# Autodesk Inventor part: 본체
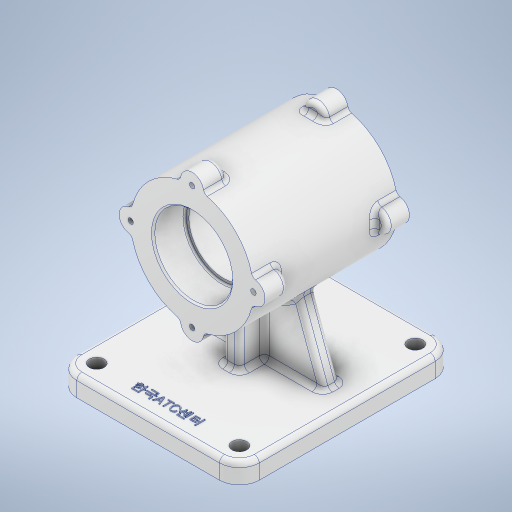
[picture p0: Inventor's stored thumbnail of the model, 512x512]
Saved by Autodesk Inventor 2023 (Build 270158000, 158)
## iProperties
Created: 2023-08
Part Number: 본체
Material: 알루미늄 6061
Document SubType Name: Modeling
Designer: asung
Density: 2.7 g/cm^3
Appearance: 알루미늄 - 평지
Author: asung
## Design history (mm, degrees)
sketch "스케치1"
  geometry: L1 (-43, 65)-(43, 65); L2 (55, 53)-(55, -53); L3 (43, -65)-(-43, -65); L4 (-55, -53)-(-55, 53); L5 (-55, 65)-(55, -65); L6 (55, 65)-(-55, -65); C1 r 4.5 at (43, 53); C2 r 4.5 at (-43, 53); C3 r 4.5 at (-43, -53); C4 r 4.5 at (43, -53); A1 r 12 centre (43, 53) between (55, 53) and (43, 65); A2 r 12 centre (43, -53) between (43, -65) and (55, -53); A3 r 12 centre (-43, -53) between (-55, -53) and (-43, -65); A4 r 12 centre (-43, 53) between (-43, 65) and (-55, 53); 1 further point
  constraints: 12 end point, 8 centre point, 8 point on circle, 8 point on line, 8 tangent, 4 coincident, 3 equal radius, 2 midpoint, 2 parallel, 1 horizontal, 1 perpendicular
  dimensions: "d0" = 110 distance of L5.end L6.end; "d1" = 130 distance of L6.start L5.end; "d2" = 12 radius of A1; "d3" = 9 diameter of C1; "d4" = 9 diameter of C2; "d5" = 9 diameter of C3; "d6" = 9 diameter of C4
extrude "돌출1" new body sketch "스케치1" distance "d7" = 12; taper "d8" = 0 deg
fillet "모깎기1" dims "d9" = 3
node "작업 평면1"
sketch "스케치2"
  geometry: L1 (-9, 12)-(95, 12) reference; L2 (98, 9)-(98, 0) reference; L3 (98, 0)-(-12, 0) reference; L4 (-12, 0)-(-12, 9) reference; L5 (86, 0)-(0, 0) reference; L6 (43, 0)-(43, 82); C1 r 37 at (43, 82); A1 r 3 centre (-9, 9) between (-9, 12) and (-12, 9) reference; A2 r 3 centre (95, 9) between (98, 9) and (95, 12) reference
  constraints: 2 end point, 1 centre point, 1 coincident, 1 vertical
  dimensions: "d14" = 82 distance of L6.start L6.end; "d15" = 37 radius of C1
extrude "돌출2" join sketch "스케치2" stored distance "d16" = 87; taper "d17" = 0 deg
sketch "스케치3"
  geometry: C1 r 37 at (0, 0) reference; C2 r 7 at (0, 37); 2 further points
  constraints: 1 centre point, 1 vertical alignment, 1 other
  dimensions: "d18" = 7 radius of C2
extrude "돌출3" join sketch "스케치3" distance "d19" = 14; taper "d20" = 0 deg
sketch "스케치4"
  geometry: C1 r 37 at (0, 0) reference; C2 r 7 at (0, 37); 2 further points
  constraints: 1 centre point, 1 vertical alignment, 1 other
  dimensions: "d24" = 7 radius of C2
extrude "돌출4" join sketch "스케치4" distance "d25" = 14; taper "d26" = 0 deg
fillet "모깎기2" dims "d30" = 3
fillet "모깎기3" dims "d34" = 3
sketch "스케치5"
  geometry: A1 r 37 centre (43, 82) between (78.863, 91.104) and (52.104, 117.863) reference; 2 further points
  constraints: 1 coincident
hole "구멍1" sketch "스케치5" at (43, 82) diameter "d38" = 42; stored, may be unused: countersink angle "d42" = 90 deg, drill point angle "d44" = 0 deg; dims "d39" = 8, "d40" = 47, "d41" = 19, "d43" = 50
sketch "스케치6"
  geometry: A1 r 37 centre (-43, 82) between (-52.104, 117.863) and (-78.863, 91.104) reference; 2 further points
  constraints: 1 coincident
hole "구멍2" sketch "스케치6" at (-43, 82) diameter "d45" = 42; stored, may be unused: countersink angle "d49" = 90 deg, drill point angle "d51" = 0 deg; dims "d46" = 6, "d47" = 47, "d48" = 19, "d50" = 50
fillet "모깎기4" dims "d52" = 1
chamfer "모따기1" distance "d53" = 1; stored, may be unused: second distance "d54" = 2, angle "d55" = 45 deg
sketch "스케치7"
  geometry: A1 r 7 centre (43, 119) between (49.889, 120.239) and (36.111, 120.239) reference; A2 r 7 centre (6, 82) between (4.761, 88.889) and (4.761, 75.111) reference; A3 r 7 centre (80, 82) between (81.239, 75.111) and (81.239, 88.889) reference; A4 r 7 centre (43, 45) between (36.111, 43.761) and (49.889, 43.761) reference; 5 further points
  constraints: 4 coincident
hole "구멍3" sketch "스케치7" at (43, 119), (6, 82), (80, 82), (43, 45) diameter "d56" = 3.242; stored, may be unused: countersink angle "d60" = 90 deg, drill point angle "d62" = 118 deg; dims "d57" = 8, "d58" = 47, "d59" = 19, "d61" = 10
sketch "스케치8"
  geometry: A1 r 7 centre (-43, 119) between (-36.111, 120.239) and (-49.889, 120.239) reference; A2 r 7 centre (-6, 82) between (-4.761, 75.111) and (-4.761, 88.889) reference; A3 r 7 centre (-43, 45) between (-49.889, 43.761) and (-36.111, 43.761) reference; A4 r 7 centre (-80, 82) between (-81.239, 88.889) and (-81.239, 75.111) reference; 5 further points
  constraints: 4 coincident
hole "구멍4" sketch "스케치8" at (-43, 119), (-6, 82), (-43, 45), (-80, 82) diameter "d63" = 3.242; stored, may be unused: countersink angle "d67" = 90 deg, drill point angle "d69" = 118 deg; dims "d64" = 8, "d65" = 4, "d66" = 2, "d68" = 10
sketch "스케치9"
  geometry: L1 (52, -53)-(52, 53) reference; L2 (43, 62)-(-43, 62) reference; L3 (-52, 53)-(-52, -53) reference; L4 (-43, -62)-(43, -62) reference; L5 (-5, -15)-(5, -15); L6 (5, -15)-(5, 25); L7 (5, 25)-(-5, 25); L8 (-5, 25)-(-5, -15); L9 (-43, -65)-(43, -65) reference; L10 (-55, 53)-(-55, -53) reference; C1 r 4.5 at (-43, -53) reference; C2 r 4.5 at (43, -53) reference; C3 r 4.5 at (43, 53) reference; C4 r 4.5 at (-43, 53) reference; A1 r 9 centre (43, -53) between (43, -62) and (52, -53) reference; A2 r 9 centre (43, 53) between (52, 53) and (43, 62) reference; A3 r 9 centre (-43, 53) between (-43, 62) and (-52, 53) reference; A4 r 9 centre (-43, -53) between (-52, -53) and (-43, -62) reference; 3 further points
  constraints: 8 end point, 2 midpoint, 2 parallel, 1 horizontal, 1 perpendicular
  dimensions: "d70" = 10 distance of L7.end L6.end; "d71" = 40 distance of L6.end L5.end; "d72" = 70 distance from line of point (-5, 5) L9; "d73" = 55 distance from line of point (0, 25) L10
extrude "돌출5" join sketch "스케치9" stored distance "d74" = 14; taper "d75" = 0 deg
node "작업 평면4"
sketch "스케치10"
  geometry: L1 (-9, 12)-(38, 12) reference; L2 (38, 12)-(38, 45.339) reference; L3 (48, 45.339)-(48, 12) reference; L4 (48, 12)-(95, 12) reference; L5 (98, 9)-(98, 0) reference; L6 (98, 0)-(-12, 0) reference; L7 (-12, 0)-(-12, 9) reference; L8 (0, 12)-(86, 12) reference; L9 (2, 12)-(19.586, 60.316); L10 (84, 12)-(67.029, 58.627); C1 r 21 at (43, 82) reference; A1 r 3 centre (-9, 9) between (-9, 12) and (-12, 9) reference; A2 r 37 centre (43, 82) between (48, 45.339) and (38, 45.339) reference; A3 r 3 centre (95, 9) between (98, 9) and (95, 12) reference; 2 further points
  constraints: 4 end point, 2 point on line, 1 midpoint
  dimensions: "d76" = 14 distance from line of L9.start L7; "d77" = 14 horizontal distance of L10.start point (98, 4.5); "d78" = 110 deg angle of L10 L4; "d79" = 110 deg angle of L9 L1
  node "절단 모서리 투영3"
feature "리브1" dims "d80" = 1, "d81" = 10, "d82" = 0, "d83" = 0, "d84" = 1, "d85" = 1
feature "리브2" dims "d86" = 1, "d87" = 10, "d88" = 0, "d89" = 0, "d90" = 1, "d91" = 1
fillet "모깎기5" dims "d92" = 3
fillet "모깎기6" dims "d93" = 3
sketch "스케치11"
  geometry: L1 (55, -53)-(55, 53) reference; L2 (40.282, 7)-(40.282, 3) reference; L3 (-36.716, -3)-(-8, -3) reference; L4 (-8, -3)-(-8, -12) reference; L5 (-2, -18)-(2, -18) reference; L6 (8, -12)-(8, -3) reference; L7 (8, -3)-(36.716, -3) reference; L8 (43.101, 3)-(43.101, 7) reference; L9 (36.716, 13)-(8, 13) reference; L10 (8, 13)-(8, 22) reference; L11 (2, 28)-(-2, 28) reference; L12 (-8, 22)-(-8, 13) reference; L13 (-8, 13)-(-36.716, 13) reference; L14 (-43.101, 7)-(-43.101, 3) reference; L15 (52, -53)-(52, 53) reference; L16 (43, 62)-(-43, 62) reference; L17 (-52, 53)-(-52, -53) reference; L18 (-43, -62)-(43, -62) reference; C1 r 4.5 at (-43, -53) reference; C2 r 4.5 at (43, -53) reference; C3 r 4.5 at (43, 53) reference; C4 r 4.5 at (-43, 53) reference; A1 r 6 centre (-2, -12) between (-8, -12) and (-2, -18) reference; A2 r 6 centre (2, -12) between (2, -18) and (8, -12) reference; A3 r 6 centre (2, 22) between (8, 22) and (2, 28) reference; A4 r 6 centre (-2, 22) between (-2, 28) and (-8, 22) reference; A5 r 9 centre (43, -53) between (43, -62) and (52, -53) reference; A6 r 9 centre (43, 53) between (52, 53) and (43, 62) reference; A7 r 9 centre (-43, 53) between (-43, 62) and (-52, 53) reference; A8 r 9 centre (-43, -53) between (-52, -53) and (-43, -62) reference; 5 further points
  constraints: 3 midpoint, 1 vertical alignment, 5 other
feature "엠보싱1" sketch "스케치11" dims "d0" = 110, "d1" = 130, "d2" = 12, "d3" = 9, "d4" = 9, "d5" = 9, "d6" = 9, "d96" = 0.5, "d97" = 0
feature "ѡ耀ѣ耀ѥ耀ѧ耀ѩ耀ѫ耀ѭ耀ѯ耀" dims "d0" = 110, "d1" = 130, "d2" = 12, "d3" = 9, "d4" = 9, "d5" = 9, "d6" = 9, "d7" = 12, "d8" = 0, "d9" = 3, "d10" = -70, "d14" = 82, "d15" = 37, "d16" = 87, "d17" = 0, "d18" = 7, "d19" = 14, "d20" = 0, "d21" = 40, "d22" = 360 deg, "d24" = 7, "d25" = 14, "d26" = 0, "d27" = 40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
node "솔리드1"
pattern_circular "원형 패턴1" dims angle "d22" = 360 deg
pattern_circular "원형 패턴2" dims angle "d28" = 360 deg
pattern_circular "원형 패턴3" dims angle "d32" = 360 deg
pattern_circular "원형 패턴4" dims angle "d36" = 360 deg
node "투영된 루프1"
node "투영된 루프2"
node "절단 모서리 투영1"
node "절단 모서리 투영2"
node "절단 모서리 투영4"
feature "A9D066F2-1C7D-4E18-AEED-F7BC21143FA4" dims "d38" = 42, "d39" = 8, "d40" = 47, "d41" = 19, "d42" = 90 deg, "d43" = 50, "d44" = 0
